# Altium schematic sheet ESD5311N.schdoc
size 127 x 101 mm
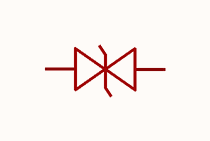
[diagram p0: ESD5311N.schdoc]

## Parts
U?  esd5311n  [DFN1006-2L-BI]  (value not drawn)

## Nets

Not connected (* = marked no-connect by the designer): U? 1 2

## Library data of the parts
U? = esd5311n: 极性:双向;反向截止电压(Vrwm):5V;钳位电压:15V;峰值脉冲电流(Ipp):4A;峰值脉冲功率(Ppp):70W;击穿电压:7.5V;; Manufacturer: TECH PUBLIC(台舟); AddInBom: yes; ModelId: 2bdbcca3b35b49c5a8ae725a08658930; ModelTransform: 40.1574,24.4094,0,0,0,0,0,0,0; Polarity: 双向; Reverse Stand-Off Voltage (Vrwm): 5V; Clamping Voltage: 15V; Peak Pulse Current (Ipp): 4A; Peak Pulse Power Dissipation (Ppp): 70W; Voltage - Breakdown: 7.5V; Reverse Leakage Current (Ir): 80nA; Number of Channels: 单路; level of protection: IEC 61000-4-5；IEC 61000-4-2; Junction Capacitance: 0.3pF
